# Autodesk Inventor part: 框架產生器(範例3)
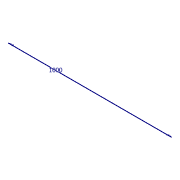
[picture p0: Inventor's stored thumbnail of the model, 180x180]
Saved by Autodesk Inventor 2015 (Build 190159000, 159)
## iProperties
Created: 2019-08
Part Number: 框架產生器(範例3)
Material: 一般
Document SubType Name: Modeling
Designer: Kuan_Lun Hsu
Density: 1 g/cm^3
Appearance: 預設
Author: Kuan_Lun Hsu
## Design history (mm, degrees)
sketch "草圖1"
  geometry: L1 (0, 0)-(1000, 0)
  constraints: 2 end point, 1 horizontal
  dimensions: "d0" = 1000 dimension on L1.start L1.end L1; "d0" = 1000 distance of L1.start L1.end
